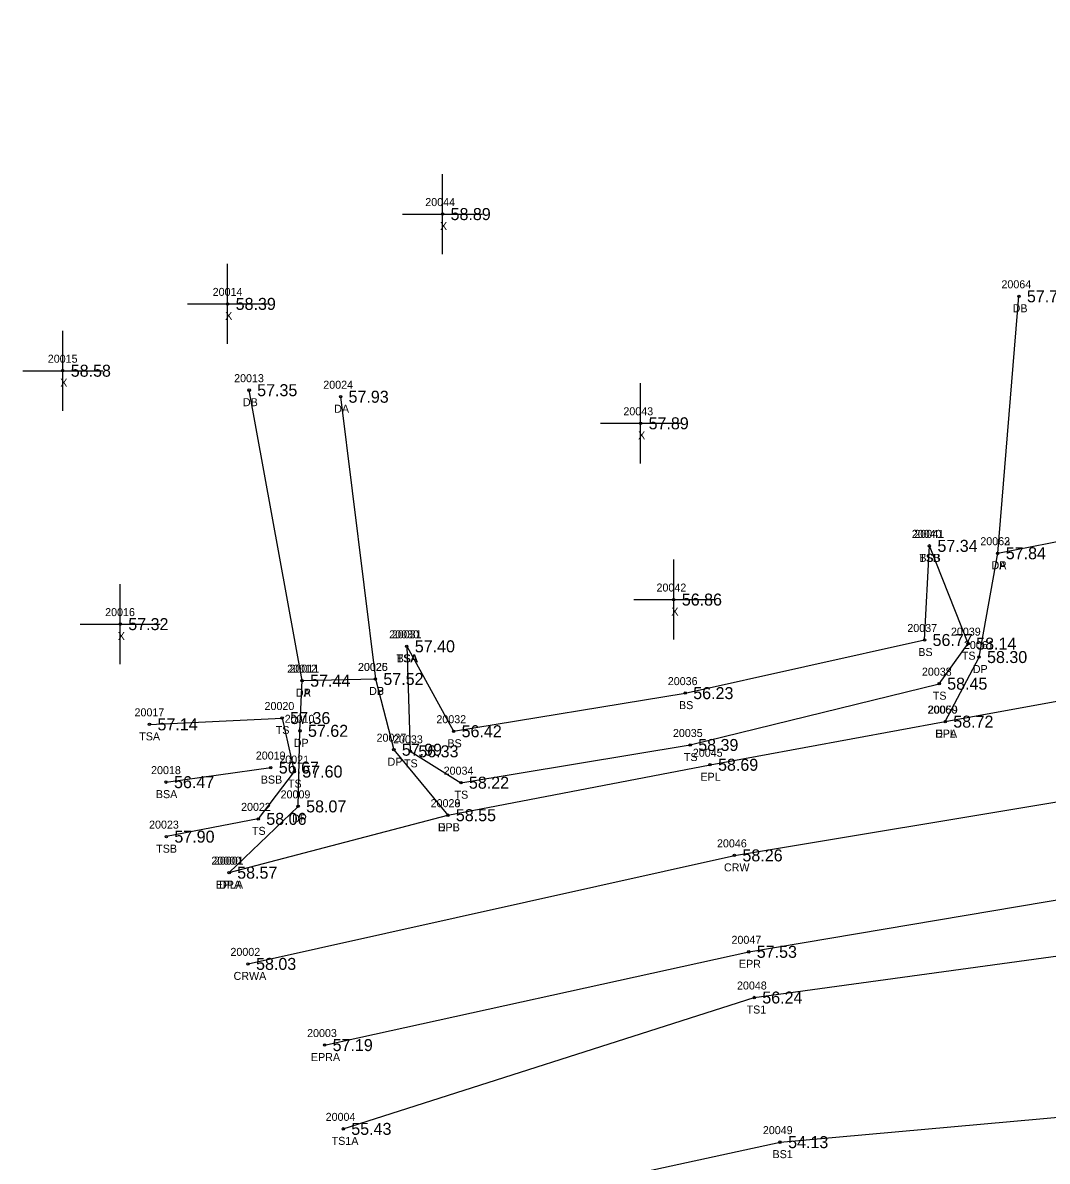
# Model space of a CAD drawing. Extents: x 2420351 to 2422725, y 845330 to 846558.
# Drawn here: x 2420350.6 to 2420478.6, y 845665.9 to 845808.1 of the extents above; entities that cross this region are included whole.
import ezdxf

# ---------------------------------------------------------------- set-up
doc = ezdxf.new("R2010")
doc.units = 0
for name, color, linetype in [('RD_DTM_BkLn1', 7, 'Continuous'), ('RD_DTM_BkLn2', 7, 'Continuous'), ('RD_DTM_BkLn_txCode', 7, 'Continuous'), ('RD_EX_Driveway', 7, 'Continuous'), ('RD_EX_Driveway_txCode', 7, 'Continuous'), ('RD_EX_Misc', 7, 'Continuous'), ('RD_EX_Misc_txCode', 7, 'Continuous'), ('RD_EX_Road', 7, 'Continuous'), ('RD_EX_Road_txCode', 7, 'Continuous'), ('RD_EX_TX_Driveway_ELEV', 7, 'Continuous'), ('RD_EX_TX_Misc_ELEV', 7, 'Continuous'), ('RD_EX_TX_Road_ELEV', 7, 'Continuous'), ('RD_HC_Survey_ELEV', 7, 'Continuous'), ('RD_HC_Survey_txCode', 7, 'Continuous'), ('RD_SMD_Locator', 7, 'Continuous')]:
    doc.layers.add(name, color=color, linetype=linetype)

msp = doc.modelspace()

# ---------------------------------------------------------------- linework, layer by layer
at = {"layer": 'RD_DTM_BkLn1'}
msp.add_lwpolyline([(2420378.71, 845690.53), (2420439.5, 845704.09), (2420489.95, 845712.49), (2420551.89, 845719.42), (2420551.95, 845719.57), (2420607.12, 845722.67), (2420682.92, 845723.04), (2420749.65, 845719.68), (2420796.31, 845715.7), (2420900.74, 845705.33), (2421018.16, 845694.11), (2421114.61, 845684.8), (2421175.74, 845680.1), (2421234.97, 845678.35), (2421292.42, 845679.46), (2421350.56, 845683.65), (2421414.53, 845692.12), (2421472.54, 845703.63), (2421533.08, 845718.31), (2421555.4, 845725.02), (2421609.81, 845741.71), (2421666.58, 845762.88), (2421744.67, 845798.22)], dxfattribs=at)
at = {"layer": 'RD_DTM_BkLn2'}
msp.add_line((2420368.46, 845713.24), (2420381.55, 845715.06), dxfattribs=at)
for points in [[(2420398.55, 845730.21), (2420398.99, 845717.09), (2420405.31, 845713.17), (2420433.97, 845717.88), (2420465.09, 845725.54), (2420468.71, 845730.54), (2420463.87, 845742.76)], [(2420398.55, 845730.21), (2420404.4, 845719.6), (2420433.35, 845724.36), (2420463.26, 845731), (2420463.87, 845742.76)], [(2420366.39, 845720.46), (2420382.97, 845721.25), (2420384.49, 845714.56), (2420379.99, 845708.65), (2420368.5, 845706.43)], [(2420390.61, 845669.92), (2420441.98, 845686.33), (2420494.54, 845693.53), (2420554.96, 845697.51), (2420607.89, 845706.33), (2420681.02, 845707.72)], [(2420391.68, 845656.64), (2420445.21, 845668.26), (2420499.47, 845673.15), (2420555.79, 845685.67), (2420611.25, 845685.1), (2420638.03, 845688.28), (2420664.95, 845679.28), (2420684.17, 845674.37), (2420751.52, 845659.06), (2420788.44, 845663), (2420892.57, 845636.64), (2420995.04, 845591.46), (2421010.85, 845555.52)]]:
    msp.add_lwpolyline(points, dxfattribs=at)
at = {"layer": 'RD_EX_Driveway'}
for p, q in [((2420472.41, 845741.84), (2420475.05, 845773.94)), ((2420385.47, 845725.92), (2420378.85, 845762.21)), ((2420390.27, 845761.39), (2420394.62, 845726.13))]:
    msp.add_line(p, q, dxfattribs=at)
for points in [[(2420465.85, 845720.8), (2420470.07, 845728.87), (2420472.41, 845741.84), (2420480.93, 845743.53), (2420483.41, 845732.63), (2420487.58, 845724.76)], [(2420376.35, 845701.93), (2420384.97, 845710.21), (2420385.2, 845719.65), (2420385.47, 845725.92), (2420394.62, 845726.13), (2420396.93, 845717.29), (2420403.68, 845709.11)]]:
    msp.add_lwpolyline(points, dxfattribs=at)
at = {"layer": 'RD_EX_Misc'}
for p, q in [((2420403.02, 845779.21), (2420403.02, 845789.21)), ((2420398.02, 845784.21), (2420408.02, 845784.21)), ((2420376.16, 845767.99), (2420376.16, 845777.99)), ((2420371.16, 845772.99), (2420381.16, 845772.99)), ((2420355.55, 845759.64), (2420355.55, 845769.64)), ((2420350.55, 845764.64), (2420360.55, 845764.64)), ((2420427.77, 845753.07), (2420427.77, 845763.07)), ((2420422.77, 845758.07), (2420432.77, 845758.07)), ((2420431.92, 845731.05), (2420431.92, 845741.05)), ((2420362.74, 845727.98), (2420362.74, 845737.98)), ((2420426.92, 845736.05), (2420436.92, 845736.05)), ((2420357.74, 845732.98), (2420367.74, 845732.98))]:
    msp.add_line(p, q, dxfattribs=at)
at = {"layer": 'RD_EX_Road'}
for points in [[(2420388.28, 845680.39), (2420441.29, 845692.04), (2420492.62, 845700.7), (2420553.92, 845707.41), (2420607.69, 845710.85), (2420682.38, 845711.26), (2420749.44, 845707.27), (2420795.12, 845703.44), (2420900.28, 845693.42), (2421017.17, 845682.19), (2421113.9, 845672.97), (2421174.87, 845668.16), (2421234.59, 845666.13), (2421293, 845667.25), (2421351.24, 845671.5), (2421419.82, 845681.17), (2421463.19, 845688.63), (2421558.82, 845713.18), (2421614.57, 845730.45), (2421670.73, 845751.42), (2421735.61, 845780.5), (2421750.75, 845787.87), (2421744.67, 845798.22), (2421739.21, 845808.11)], [(2420376.35, 845701.93), (2420403.68, 845709.11), (2420436.45, 845715.41), (2420465.85, 845720.8), (2420487.58, 845724.76), (2420551.29, 845731.53), (2420607.05, 845734.89), (2420658.72, 845735.59), (2420682.86, 845735.47), (2420736.67, 845732.56), (2420795.4, 845727.65), (2420889.7, 845718.98), (2420911.08, 845716.87), (2420953.91, 845713.71), (2420998.34, 845708.25), (2421018.47, 845706.55), (2421116.02, 845696.98), (2421176.98, 845692), (2421235.85, 845690.14), (2421292.32, 845691.44), (2421350.22, 845695.49), (2421412.35, 845704.28)]]:
    msp.add_lwpolyline(points, dxfattribs=at)
at = {"layer": 'RD_SMD_Locator'}
for centre in [(2420403.02, 845784.21), (2420475.05, 845773.94), (2420376.16, 845772.99), (2420355.55, 845764.64), (2420378.85, 845762.21), (2420390.27, 845761.39), (2420427.77, 845758.07), (2420463.87, 845742.76), (2420463.87, 845742.76), (2420472.41, 845741.84), (2420472.41, 845741.84), (2420431.92, 845736.05), (2420362.74, 845732.98), (2420398.55, 845730.21), (2420398.55, 845730.21), (2420463.26, 845731), (2420468.71, 845730.54), (2420470.07, 845728.87), (2420385.47, 845725.92), (2420385.47, 845725.92), (2420394.62, 845726.13), (2420394.62, 845726.13), (2420465.09, 845725.54), (2420433.35, 845724.36), (2420382.97, 845721.25), (2420366.39, 845720.46), (2420465.85, 845720.8), (2420465.85, 845720.8), (2420385.2, 845719.65), (2420404.4, 845719.6), (2420396.93, 845717.29), (2420398.99, 845717.09), (2420433.97, 845717.88), (2420381.55, 845715.06), (2420384.49, 845714.56), (2420436.45, 845715.41), (2420368.46, 845713.24), (2420405.31, 845713.17), (2420384.97, 845710.21), (2420379.99, 845708.65), (2420403.68, 845709.11), (2420403.68, 845709.11), (2420368.5, 845706.43), (2420439.5, 845704.09), (2420376.35, 845701.93), (2420376.35, 845701.93), (2420441.29, 845692.04), (2420378.71, 845690.53), (2420441.98, 845686.33), (2420388.28, 845680.39), (2420390.61, 845669.92), (2420445.21, 845668.26)]:
    msp.add_circle(centre, 0.15, dxfattribs=at)

# ---------------------------------------------------------------- texts
at = {"layer": 'RD_DTM_BkLn_txCode'}
for s, p in [('20040', (2420461.67, 845743.76)), ('20041', (2420461.99, 845743.76)), ('TSB', (2420462.6, 845740.76)), ('BSB', (2420462.61, 845740.76)), ('20037', (2420461.11, 845732)), ('20030', (2420396.35, 845731.21)), ('20031', (2420396.68, 845731.21)), ('20039', (2420466.56, 845731.54)), ('BS', (2420462.48, 845729)), ('TSA', (2420397.27, 845728.21)), ('BSA', (2420397.28, 845728.21)), ('TS', (2420467.92, 845728.54)), ('20038', (2420462.93, 845726.54)), ('20036', (2420431.17, 845725.36)), ('TS', (2420464.29, 845723.54)), ('20020', (2420380.77, 845722.25)), ('BS', (2420432.57, 845722.36)), ('20017', (2420364.52, 845721.46)), ('20032', (2420402.25, 845720.6)), ('TS', (2420382.17, 845719.25)), ('20035', (2420431.81, 845718.88)), ('TSA', (2420365.11, 845718.46)), ('20033', (2420396.83, 845718.09)), ('BS', (2420403.63, 845717.6)), ('20019', (2420379.68, 845716.06)), ('20021', (2420382.62, 845715.56)), ('TS', (2420398.2, 845715.09)), ('TS', (2420433.18, 845715.88)), ('20018', (2420366.59, 845714.24)), ('20034', (2420403.16, 845714.17)), ('BSB', (2420380.3, 845713.06)), ('TS', (2420383.7, 845712.56)), ('BSA', (2420367.19, 845711.24)), ('TS', (2420404.52, 845711.17)), ('20022', (2420377.84, 845709.65)), ('20023', (2420366.34, 845707.43)), ('TS', (2420379.2, 845706.65)), ('TSB', (2420367.23, 845704.43)), ('20048', (2420439.82, 845687.33)), ('TS1', (2420441.02, 845684.33)), ('20004', (2420388.41, 845670.92)), ('20049', (2420443.05, 845669.26)), ('TS1A', (2420389.16, 845667.92)), ('BS1', (2420444.26, 845666.26))]:
    msp.add_text(s, height=1, dxfattribs=at).set_placement(p)
at = {"layer": 'RD_EX_Driveway_txCode'}
for s, p in [('20064', (2420472.87, 845774.94)), ('DB', (2420474.27, 845771.94)), ('20013', (2420376.97, 845763.21)), ('20024', (2420388.11, 845762.39)), ('DB', (2420378.07, 845760.21)), ('DA', (2420389.48, 845759.39)), ('20062', (2420470.23, 845742.84)), ('20063', (2420470.23, 845742.84)), ('DA', (2420471.61, 845739.84)), ('DP', (2420471.63, 845739.84)), ('20061', (2420468.18, 845729.87)), ('20012', (2420383.6, 845726.92)), ('20011', (2420383.88, 845726.92)), ('20026', (2420392.44, 845727.13)), ('20025', (2420392.46, 845727.13)), ('DP', (2420469.29, 845726.87)), ('DA', (2420384.67, 845723.92)), ('DP', (2420384.69, 845723.92)), ('DB', (2420393.84, 845724.13)), ('DP', (2420393.84, 845724.13)), ('20060', (2420463.63, 845721.8)), ('20010', (2420383.29, 845720.65)), ('DP', (2420384.42, 845717.65)), ('20027', (2420394.77, 845718.29)), ('DPA', (2420464.58, 845718.8)), ('DP', (2420396.15, 845715.29)), ('20009', (2420382.78, 845711.21)), ('20028', (2420401.53, 845710.11)), ('DP', (2420384.2, 845708.21)), ('DPB', (2420402.43, 845707.11)), ('20001', (2420374.44, 845702.93)), ('DPA', (2420375.08, 845699.93))]:
    msp.add_text(s, height=1, dxfattribs=at).set_placement(p)
at = {"layer": 'RD_EX_Misc_txCode'}
for s, p in [('20044', (2420400.86, 845785.21)), ('X', (2420402.7, 845782.21)), ('20014', (2420374.29, 845773.99)), ('X', (2420375.85, 845770.99)), ('20015', (2420353.68, 845765.64)), ('X', (2420355.24, 845762.64)), ('20043', (2420425.62, 845759.07)), ('X', (2420427.46, 845756.07)), ('20042', (2420429.76, 845737.05)), ('20016', (2420360.85, 845733.98)), ('X', (2420431.61, 845734.05)), ('X', (2420362.43, 845730.98))]:
    msp.add_text(s, height=1, dxfattribs=at).set_placement(p)
at = {"layer": 'RD_EX_Road_txCode'}
for s, p in [('20059', (2420463.69, 845721.8)), ('EPL', (2420464.64, 845718.8)), ('20045', (2420434.3, 845716.41)), ('EPL', (2420435.25, 845713.41)), ('20029', (2420401.53, 845710.11)), ('EPL', (2420402.48, 845707.11)), ('20000', (2420374.12, 845702.93)), ('EPLA', (2420374.66, 845699.93)), ('20047', (2420439.13, 845693.04)), ('EPR', (2420440.06, 845690.04)), ('20003', (2420386.09, 845681.39)), ('EPRA', (2420386.57, 845678.39))]:
    msp.add_text(s, height=1, dxfattribs=at).set_placement(p)
at = {"layer": 'RD_EX_TX_Driveway_ELEV'}
for s, p in [('57.75', (2420476.05, 845773.19)), ('57.35', (2420379.85, 845761.46)), ('57.93', (2420391.27, 845760.64)), ('57.84', (2420473.41, 845741.09)), ('57.84', (2420473.41, 845741.09)), ('58.30', (2420471.07, 845728.12)), ('57.44', (2420386.47, 845725.17)), ('57.44', (2420386.47, 845725.17)), ('57.52', (2420395.62, 845725.38)), ('57.52', (2420395.62, 845725.38)), ('58.72', (2420466.85, 845720.05)), ('57.62', (2420386.2, 845718.9)), ('57.99', (2420397.93, 845716.54)), ('58.07', (2420385.97, 845709.46)), ('58.55', (2420404.68, 845708.36)), ('58.57', (2420377.35, 845701.18))]:
    msp.add_text(s, height=1.5, dxfattribs=at).set_placement(p)
at = {"layer": 'RD_EX_TX_Misc_ELEV'}
for s, p in [('58.89', (2420404.02, 845783.46)), ('58.39', (2420377.16, 845772.24)), ('58.58', (2420356.55, 845763.89)), ('57.89', (2420428.77, 845757.32)), ('57.34', (2420464.87, 845742.01)), ('57.34', (2420464.87, 845742.01)), ('56.86', (2420432.92, 845735.3)), ('57.32', (2420363.74, 845732.23)), ('56.77', (2420464.26, 845730.25)), ('58.14', (2420469.71, 845729.79)), ('57.40', (2420399.55, 845729.46)), ('57.40', (2420399.55, 845729.46)), ('58.45', (2420466.09, 845724.79)), ('56.23', (2420434.35, 845723.61)), ('57.36', (2420383.97, 845720.5)), ('57.14', (2420367.39, 845719.71)), ('56.42', (2420405.4, 845718.85)), ('58.39', (2420434.97, 845717.13)), ('56.33', (2420399.99, 845716.34)), ('56.67', (2420382.55, 845714.31)), ('57.60', (2420385.49, 845713.81)), ('56.47', (2420369.46, 845712.49)), ('58.22', (2420406.31, 845712.42)), ('58.06', (2420380.99, 845707.9)), ('57.90', (2420369.5, 845705.68)), ('56.24', (2420442.98, 845685.58)), ('55.43', (2420391.61, 845669.17)), ('54.13', (2420446.21, 845667.51))]:
    msp.add_text(s, height=1.5, dxfattribs=at).set_placement(p)
at = {"layer": 'RD_EX_TX_Road_ELEV'}
for s, p in [('58.72', (2420466.85, 845720.05)), ('58.69', (2420437.45, 845714.66)), ('58.55', (2420404.68, 845708.36)), ('58.57', (2420377.35, 845701.18)), ('57.53', (2420442.29, 845691.29)), ('57.19', (2420389.28, 845679.64))]:
    msp.add_text(s, height=1.5, dxfattribs=at).set_placement(p)
at = {"layer": 'RD_HC_Survey_ELEV'}
for s, p in [('58.26', (2420440.5, 845703.34)), ('58.03', (2420379.71, 845689.78))]:
    msp.add_text(s, height=1.5, dxfattribs=at).set_placement(p)
at = {"layer": 'RD_HC_Survey_txCode'}
for s, p in [('20046', (2420437.32, 845705.09)), ('CRW', (2420438.19, 845702.09)), ('20002', (2420376.51, 845691.53)), ('CRWA', (2420376.9, 845688.53))]:
    msp.add_text(s, height=1, dxfattribs=at).set_placement(p)

doc.saveas('drawing.dxf')
